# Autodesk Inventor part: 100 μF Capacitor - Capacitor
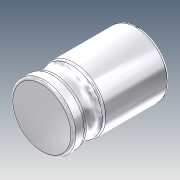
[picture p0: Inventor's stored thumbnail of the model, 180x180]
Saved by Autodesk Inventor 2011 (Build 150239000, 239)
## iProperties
Created: 2013-03
Part Number: 100 μF Capacitor - Capacitor
Document SubType Name: Modeling
Designer: Lance
Density: 2.71 g/cm^3
Material: Aluminum-6061
Mass: 1.39506 g
Surface Area: 3.6069 cm^2
Volume: 0.514781 cm^3
Author: Lance
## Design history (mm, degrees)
node "100 uF Capacitor - Basic Shape" dims "d0" = 10
node "100 uF Capacitor - Shell Shape" dims "d1" = 10
combine "Combine1"
  body "Solid2"
sketch "Sketch1"
  geometry: L1 (-3.5, 5.8)-(3.5, 5.8) reference; C1 r 0.15 at (0, 5.8); 2 further points
  constraints: 1 centre point, 1 coincident, 1 midpoint
  dimensions: "d2" = 0.3 diameter of C1
extrude "Extrusion1" cut sketch "Sketch1" stored distance "d3" = 10; taper "d4" = 0 deg
fillet "Fillet1" dims "d5" = 0.1
pattern_circular "Circular Pattern1" dims angle "d7" = 360 deg
tag "TaggingFeature1"
feature "Solid1::100 μF Capacitor - Shell Shape.ipt" dims "d1" = 10
tag "TaggingFeature2"
feature "Solid1::100 μF Capacitor - Basic Shape.ipt" dims "d0" = 10
body "Solid1"
